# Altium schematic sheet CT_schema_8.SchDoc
size 390 x 278 mm
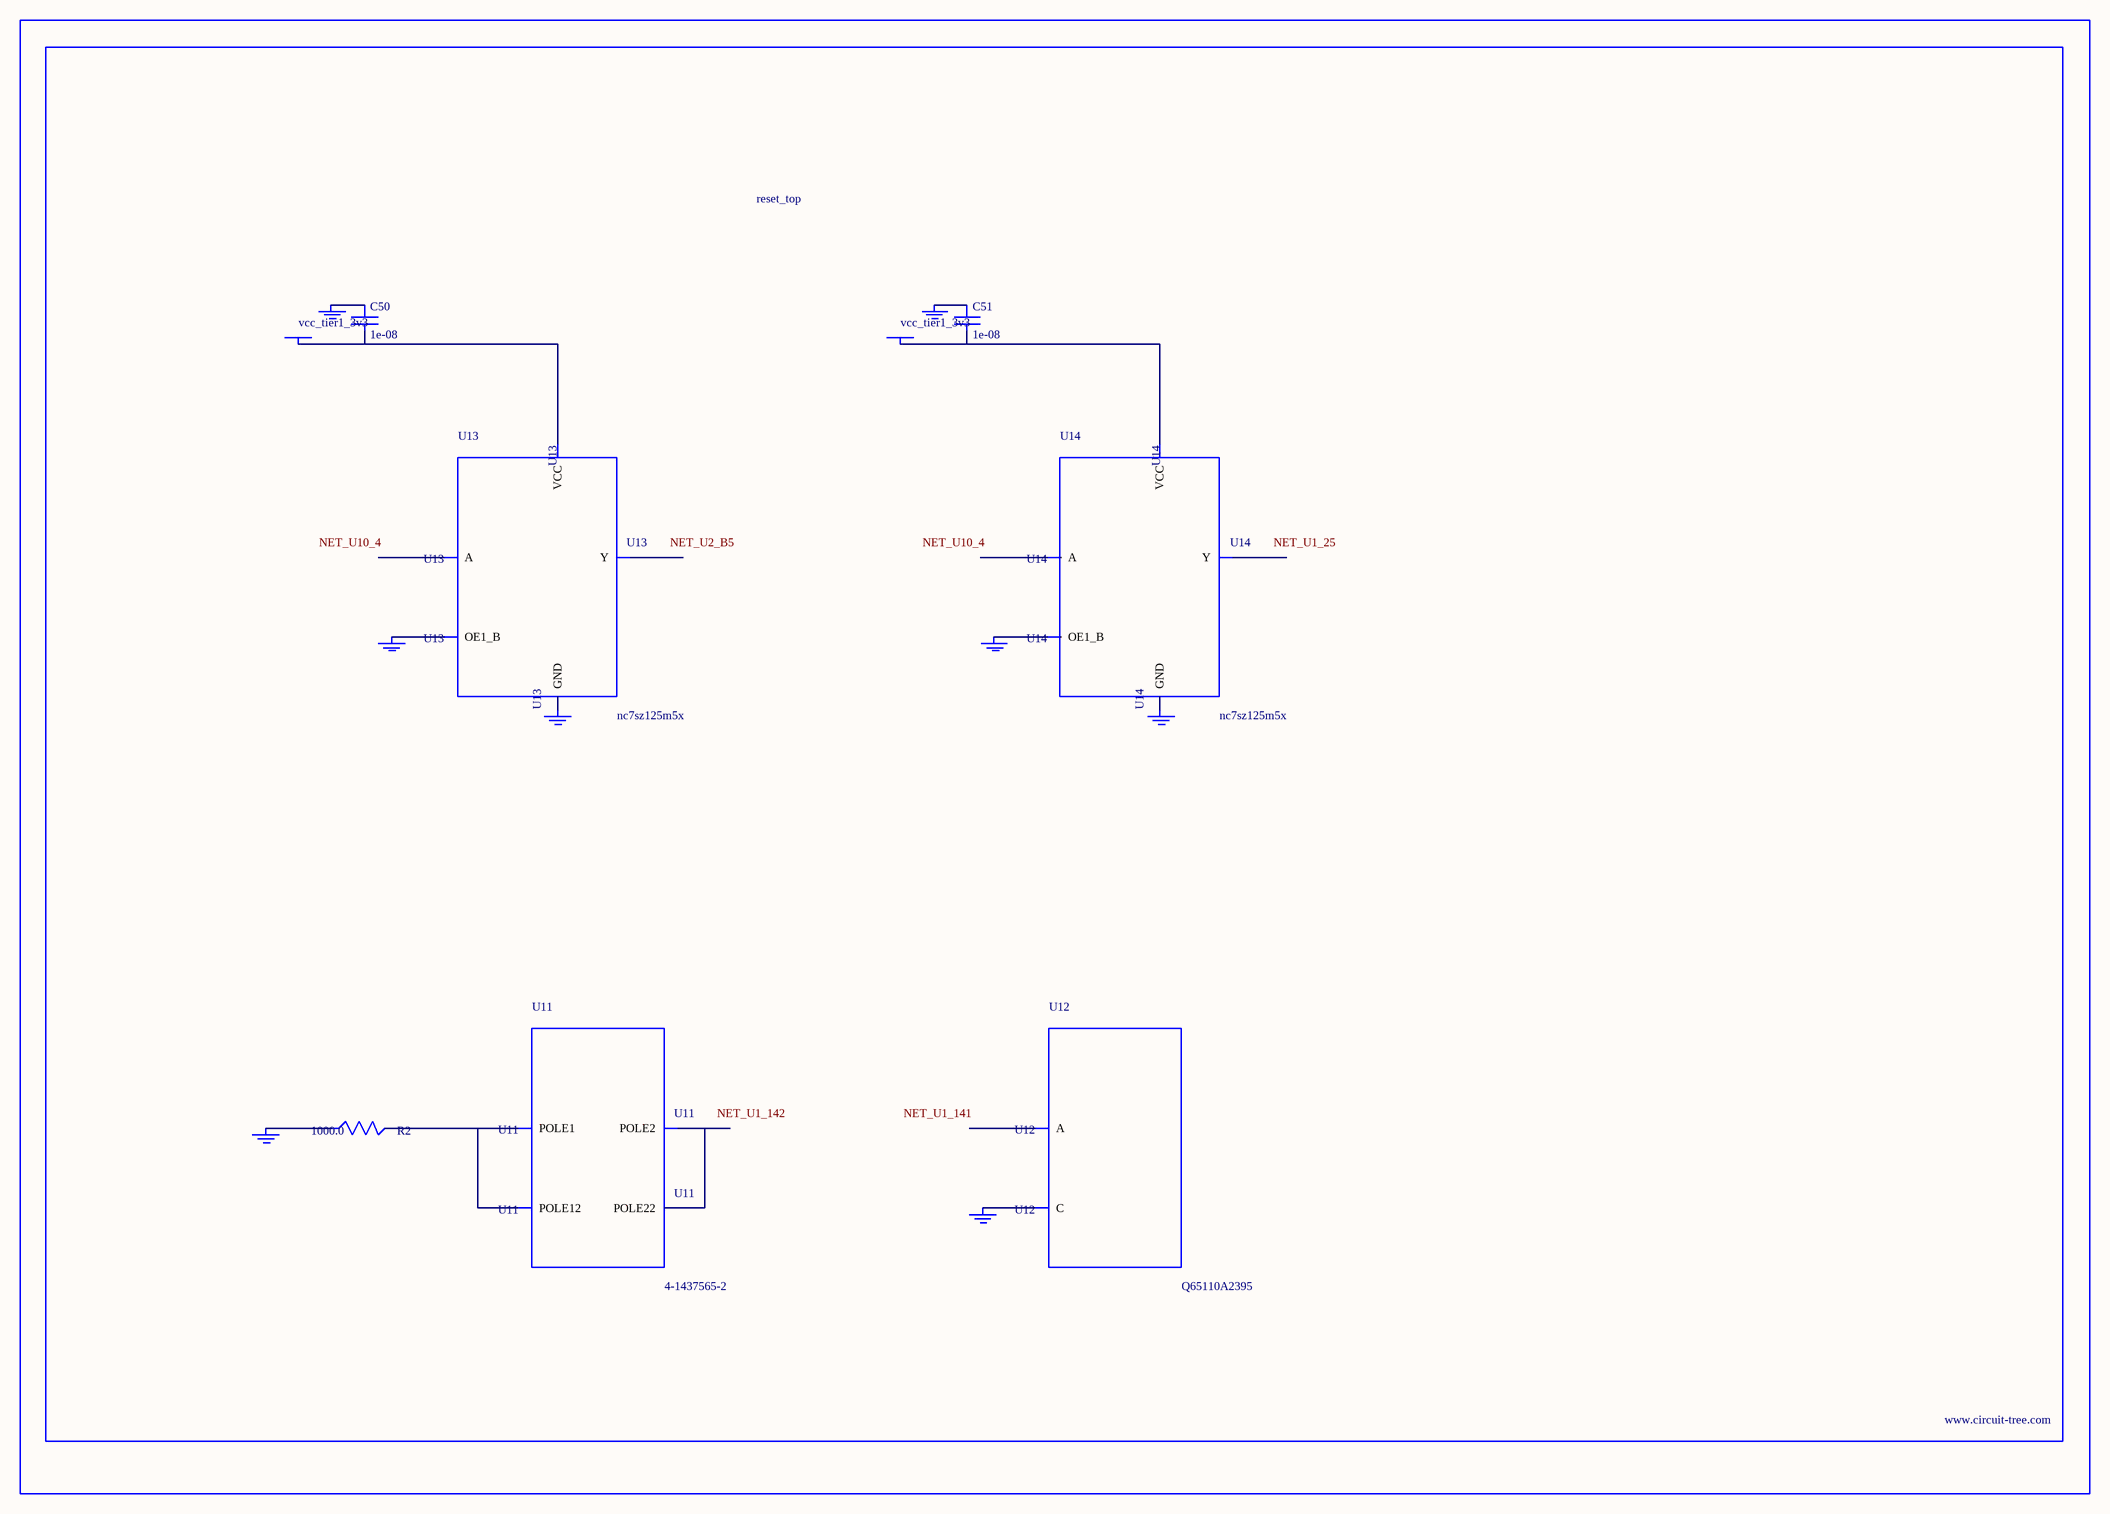
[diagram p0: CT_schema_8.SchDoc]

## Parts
BORDER7  (no value)
C50  1e-08  [C0402]
C51  1e-08  [C0402]
GND_INSTANCE_7_0  (no value)
GND_INSTANCE_7_1  (no value)
GND_INSTANCE_7_2  (no value)
GND_INSTANCE_7_3  (no value)
GND_INSTANCE_7_4  (no value)
GND_INSTANCE_7_5  (no value)
GND_INSTANCE_7_6  (no value)
GND_INSTANCE_7_7  (no value)
POWER_INSTANCE_7_0  vcc_tier1_3v3
POWER_INSTANCE_7_1  vcc_tier1_3v3
R2  1000.0  [R0603]
U11  4-1437565-2  [SW_4-1437565-2]
U12  Q65110A2395  [LGM67K-G1J2-24-Z]
U13  nc7sz125m5x  [NC7SZ125M5X]
U14  nc7sz125m5x  [NC7SZ125M5X]

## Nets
NetC50_1: C50.1 GND_INSTANCE_7_2.0(GND)
NetC50_2: C50.2 POWER_INSTANCE_7_0.0(PWR) U13.5(VCC)
NetC51_1: C51.1 GND_INSTANCE_7_5.0(GND)
NetC51_2: C51.2 POWER_INSTANCE_7_1.0(PWR) U14.5(VCC)
NetGND_INSTANCE_7_0_0: GND_INSTANCE_7_0.0(GND) R2.1
NetGND_INSTANCE_7_1_0: GND_INSTANCE_7_1.0(GND) U12.C
NetGND_INSTANCE_7_3_0: GND_INSTANCE_7_3.0(GND) U13.1(OE1_B)
NetGND_INSTANCE_7_4_0: GND_INSTANCE_7_4.0(GND) U13.3(GND)
NetGND_INSTANCE_7_6_0: GND_INSTANCE_7_6.0(GND) U14.1(OE1_B)
NetGND_INSTANCE_7_7_0: GND_INSTANCE_7_7.0(GND) U14.3(GND)
NetR2_2: R2.2 U11.1(POLE1) U11.2(POLE12)
NetU11_3: U11.3(POLE2) U11.4(POLE22)

Not connected (* = marked no-connect by the designer): U12 A; U13 2(A) 4(Y); U14 2(A) 4(Y)

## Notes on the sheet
- Labels drawn without touching a wire or pin: NET_U1_25, NET_U1_141, NET_U1_142, NET_U2_B5, NET_U10_4

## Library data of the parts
BORDER7 = BORDER_PAGE7
C50 C51 = C0402C103K3RAC
GND_INSTANCE_7_0-GND_INSTANCE_7_7 = GND
POWER_INSTANCE_7_0 POWER_INSTANCE_7_1 = PWR
R2 = RC0603JR-071KL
